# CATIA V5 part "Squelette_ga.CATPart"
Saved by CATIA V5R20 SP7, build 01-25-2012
Part number: Squelette_ga
Publications: "Plan.2", "Droite.5", "Droite.6"
Bounding box of the stored display mesh (mm): x 0 to 20, y -70.711 to 0, z 0 to 0
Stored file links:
  G:\bon\Nouveau dossier\Squelette_ga.CATPart
  C:\Documents and Settings\cgirerd\Bureau\Copie de Copie de Nouveau dossier\765.CATProduct
  G:\bon\Nouveau dossier\mecanism.skl.CATProduct
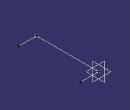
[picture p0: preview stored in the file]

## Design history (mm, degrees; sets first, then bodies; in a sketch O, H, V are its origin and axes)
Set1
  Point1 "G": linked copy from another document
  Point2 "A": linked copy from another document
  Plane1: linked copy from another document
Set2
  Line1: type PtPt, FirstPoint Point1, SecondPoint Point2
  Line2: type Normal, RefPoint Point1, RefSkin Plane1, Start 0, End 20
  Line3: type Normal, RefPoint Point2, RefSkin Plane1, Start 0, End 20
Body1 (main body)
